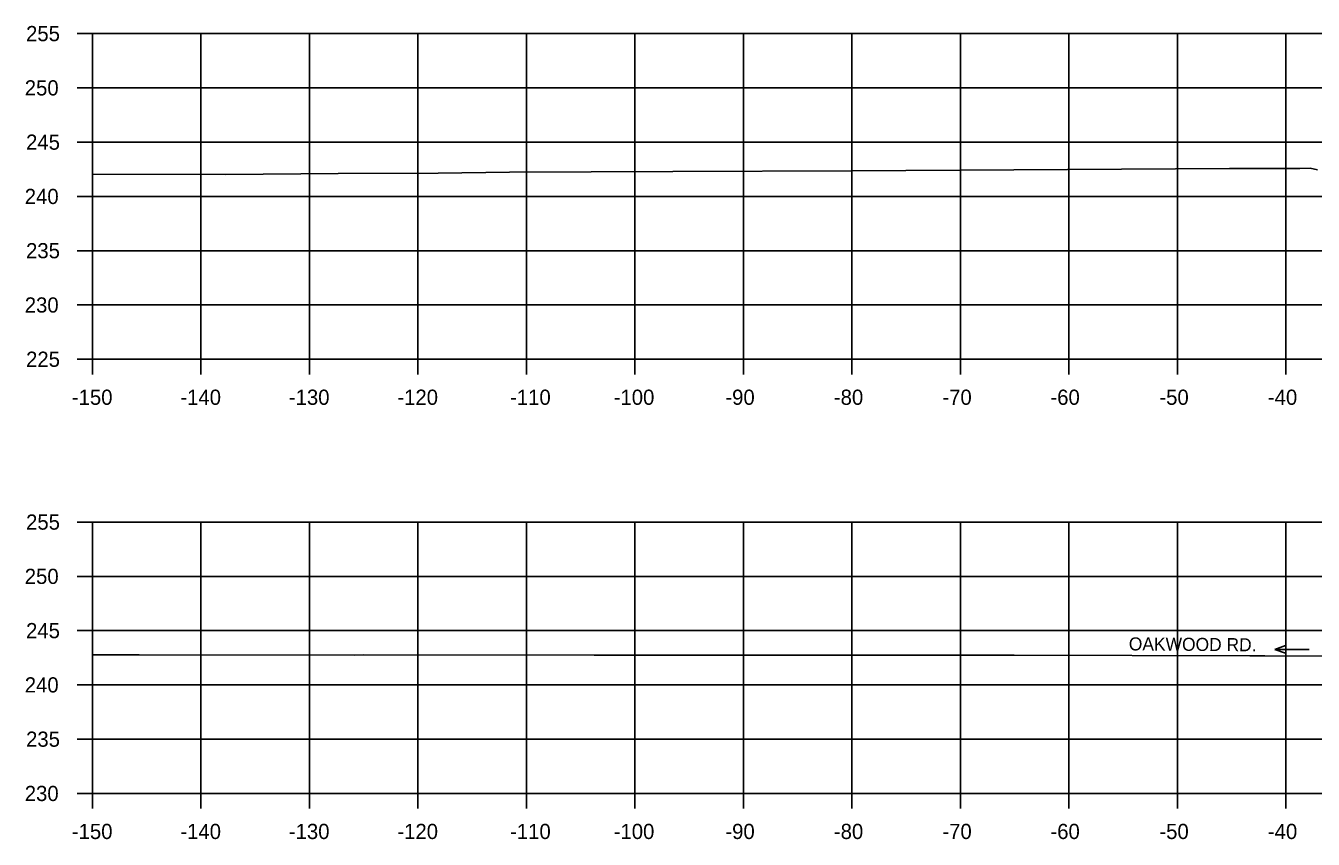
# Model space of a CAD drawing. Extents: x 1369627 to 1374022, y 380035 to 398173.
# Drawn here: x 1371382.7 to 1371501.4, y 383045.3 to 383120.2 of the extents above; entities that cross this region are included whole.
import ezdxf

# ---------------------------------------------------------------- set-up
doc = ezdxf.new("R2010")
doc.units = 0
for name, color, linetype in [('R_Alt Surface', 7, 'Continuous'), ('R_Axis', 7, 'Continuous'), ('R_Axis Annot', 7, 'Continuous'), ('R_Exist Surface', 7, 'Continuous'), ('R_Grid', 7, 'Continuous'), ('R_Water Annot', 7, 'Continuous')]:
    doc.layers.add(name, color=color, linetype=linetype)

msp = doc.modelspace()

# ---------------------------------------------------------------- linework, layer by layer
at = {"layer": 'R_Axis'}
for p, q in [((1371387.45, 383119.49), (1371388.85, 383119.49)), ((1371388.85, 383089.49), (1371388.85, 383119.49)), ((1371387.45, 383114.49), (1371388.85, 383114.49)), ((1371387.45, 383109.49), (1371388.85, 383109.49)), ((1371387.45, 383104.49), (1371388.85, 383104.49)), ((1371387.45, 383099.49), (1371388.85, 383099.49)), ((1371387.45, 383094.49), (1371388.85, 383094.49)), ((1371387.45, 383089.49), (1371388.85, 383089.49)), ((1371388.85, 383089.49), (1371688.85, 383089.49)), ((1371388.85, 383088.09), (1371388.85, 383089.49)), ((1371398.85, 383088.09), (1371398.85, 383089.49)), ((1371408.85, 383088.09), (1371408.85, 383089.49)), ((1371418.85, 383088.09), (1371418.85, 383089.49)), ((1371428.85, 383088.09), (1371428.85, 383089.49)), ((1371438.85, 383088.09), (1371438.85, 383089.49)), ((1371448.85, 383088.09), (1371448.85, 383089.49)), ((1371458.85, 383088.09), (1371458.85, 383089.49)), ((1371468.85, 383088.09), (1371468.85, 383089.49)), ((1371478.85, 383088.09), (1371478.85, 383089.49)), ((1371488.85, 383088.09), (1371488.85, 383089.49)), ((1371498.85, 383088.09), (1371498.85, 383089.49)), ((1371387.45, 383074.49), (1371388.85, 383074.49)), ((1371388.85, 383049.49), (1371388.85, 383074.49)), ((1371387.45, 383069.49), (1371388.85, 383069.49)), ((1371387.45, 383064.49), (1371388.85, 383064.49)), ((1371387.45, 383059.49), (1371388.85, 383059.49)), ((1371387.45, 383054.49), (1371388.85, 383054.49)), ((1371387.45, 383049.49), (1371388.85, 383049.49)), ((1371388.85, 383049.49), (1371688.85, 383049.49)), ((1371388.85, 383048.09), (1371388.85, 383049.49)), ((1371398.85, 383048.09), (1371398.85, 383049.49)), ((1371408.85, 383048.09), (1371408.85, 383049.49)), ((1371418.85, 383048.09), (1371418.85, 383049.49)), ((1371428.85, 383048.09), (1371428.85, 383049.49)), ((1371438.85, 383048.09), (1371438.85, 383049.49)), ((1371448.85, 383048.09), (1371448.85, 383049.49)), ((1371458.85, 383048.09), (1371458.85, 383049.49)), ((1371468.85, 383048.09), (1371468.85, 383049.49)), ((1371478.85, 383048.09), (1371478.85, 383049.49)), ((1371488.85, 383048.09), (1371488.85, 383049.49)), ((1371498.85, 383048.09), (1371498.85, 383049.49))]:
    msp.add_line(p, q, dxfattribs=at)
at = {"layer": 'R_Exist Surface'}
for points in [[(1371388.85, 383106.54), (1371401.15, 383106.5), (1371411.49, 383106.6), (1371420.72, 383106.63), (1371427.29, 383106.73), (1371442.36, 383106.8), (1371458.84, 383106.86), (1371493.66, 383107.07), (1371499.17, 383107.06), (1371500.15, 383107.06), (1371501.1, 383107.08), (1371501.77, 383106.94)], [(1371388.85, 383062.26), (1371391.49, 383062.26), (1371393.16, 383062.26), (1371412.98, 383062.24), (1371413.85, 383062.25), (1371413.85, 383062.25), (1371435.1, 383062.22), (1371435.14, 383062.22), (1371441.28, 383062.23), (1371454.32, 383062.23), (1371454.48, 383062.23), (1371473.43, 383062.24), (1371473.82, 383062.24), (1371495.54, 383062.18), (1371496.9, 383062.18), (1371517.7, 383062.13)]]:
    msp.add_lwpolyline(points, dxfattribs=at)
at = {"layer": 'R_Grid'}
for p, q in [((1371388.85, 383119.49), (1371688.85, 383119.49)), ((1371388.85, 383089.49), (1371388.85, 383119.49)), ((1371398.85, 383089.49), (1371398.85, 383119.49)), ((1371408.85, 383089.49), (1371408.85, 383119.49)), ((1371418.85, 383089.49), (1371418.85, 383119.49)), ((1371428.85, 383089.49), (1371428.85, 383119.49)), ((1371438.85, 383089.49), (1371438.85, 383119.49)), ((1371448.85, 383089.49), (1371448.85, 383119.49)), ((1371458.85, 383089.49), (1371458.85, 383119.49)), ((1371468.85, 383089.49), (1371468.85, 383119.49)), ((1371478.85, 383089.49), (1371478.85, 383119.49)), ((1371488.85, 383089.49), (1371488.85, 383119.49)), ((1371498.85, 383089.49), (1371498.85, 383119.49)), ((1371388.85, 383114.49), (1371688.85, 383114.49)), ((1371388.85, 383109.49), (1371688.85, 383109.49)), ((1371388.85, 383104.49), (1371688.85, 383104.49)), ((1371388.85, 383099.49), (1371688.85, 383099.49)), ((1371388.85, 383094.49), (1371688.85, 383094.49)), ((1371388.85, 383089.49), (1371688.85, 383089.49)), ((1371388.85, 383074.49), (1371688.85, 383074.49)), ((1371388.85, 383049.49), (1371388.85, 383074.49)), ((1371398.85, 383049.49), (1371398.85, 383074.49)), ((1371408.85, 383049.49), (1371408.85, 383074.49)), ((1371418.85, 383049.49), (1371418.85, 383074.49)), ((1371428.85, 383049.49), (1371428.85, 383074.49)), ((1371438.85, 383049.49), (1371438.85, 383074.49)), ((1371448.85, 383049.49), (1371448.85, 383074.49)), ((1371458.85, 383049.49), (1371458.85, 383074.49)), ((1371468.85, 383049.49), (1371468.85, 383074.49)), ((1371478.85, 383049.49), (1371478.85, 383074.49)), ((1371488.85, 383049.49), (1371488.85, 383074.49)), ((1371498.85, 383049.49), (1371498.85, 383074.49)), ((1371388.85, 383069.49), (1371688.85, 383069.49)), ((1371388.85, 383064.49), (1371688.85, 383064.49)), ((1371388.85, 383059.49), (1371688.85, 383059.49)), ((1371388.85, 383054.49), (1371688.85, 383054.49)), ((1371388.85, 383049.49), (1371688.85, 383049.49))]:
    msp.add_line(p, q, dxfattribs=at)
at = {"layer": 'R_Water Annot'}
for p, q in [((1371497.84, 383062.76), (1371498.81, 383063.11)), ((1371500.99, 383062.76), (1371497.84, 383062.76)), ((1371497.84, 383062.76), (1371498.81, 383062.41))]:
    msp.add_line(p, q, dxfattribs=at)

# ---------------------------------------------------------------- texts
at = {"layer": 'R_Alt Surface'}
msp.add_text('OAKWOOD RD.', height=1.2, rotation=359.5795, dxfattribs=at).set_placement((1371484.37, 383062.67))
at = {"layer": 'R_Axis Annot'}
for s, p in [('255', (1371382.74, 383118.79)), ('250', (1371382.62, 383113.79)), ('245', (1371382.74, 383108.79)), ('240', (1371382.62, 383103.79)), ('235', (1371382.74, 383098.79)), ('230', (1371382.62, 383093.79)), ('225', (1371382.74, 383088.79)), ('-150', (1371386.96, 383085.29)), ('-140', (1371396.96, 383085.29)), ('-130', (1371406.96, 383085.29)), ('-120', (1371416.96, 383085.29)), ('-110', (1371427.35, 383085.29)), ('-100', (1371436.9, 383085.29)), ('-90', (1371447.19, 383085.29)), ('-80', (1371457.19, 383085.29)), ('-70', (1371467.19, 383085.29)), ('-60', (1371477.15, 383085.29)), ('-50', (1371487.19, 383085.29)), ('-40', (1371497.19, 383085.29)), ('255', (1371382.74, 383073.79)), ('250', (1371382.62, 383068.79)), ('245', (1371382.74, 383063.79)), ('240', (1371382.62, 383058.79)), ('235', (1371382.74, 383053.79)), ('230', (1371382.62, 383048.79)), ('-150', (1371386.96, 383045.29)), ('-140', (1371396.96, 383045.29)), ('-130', (1371406.96, 383045.29)), ('-120', (1371416.96, 383045.29)), ('-110', (1371427.35, 383045.29)), ('-100', (1371436.9, 383045.29)), ('-90', (1371447.19, 383045.29)), ('-80', (1371457.19, 383045.29)), ('-70', (1371467.19, 383045.29)), ('-60', (1371477.15, 383045.29)), ('-50', (1371487.19, 383045.29)), ('-40', (1371497.19, 383045.29))]:
    msp.add_text(s, height=1.4, dxfattribs=at).set_placement(p)

doc.saveas('drawing.dxf')
